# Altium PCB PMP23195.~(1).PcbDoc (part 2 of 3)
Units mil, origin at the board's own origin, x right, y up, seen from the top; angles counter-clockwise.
Board outline 3600 x 3000 mil, 4 copper layers (Top Layer, Signal Layer 1, Signal Layer 2, Bottom Layer), stack 39.6 mil thick; 143 components, 62 nets, 279 pads, 97 vias.
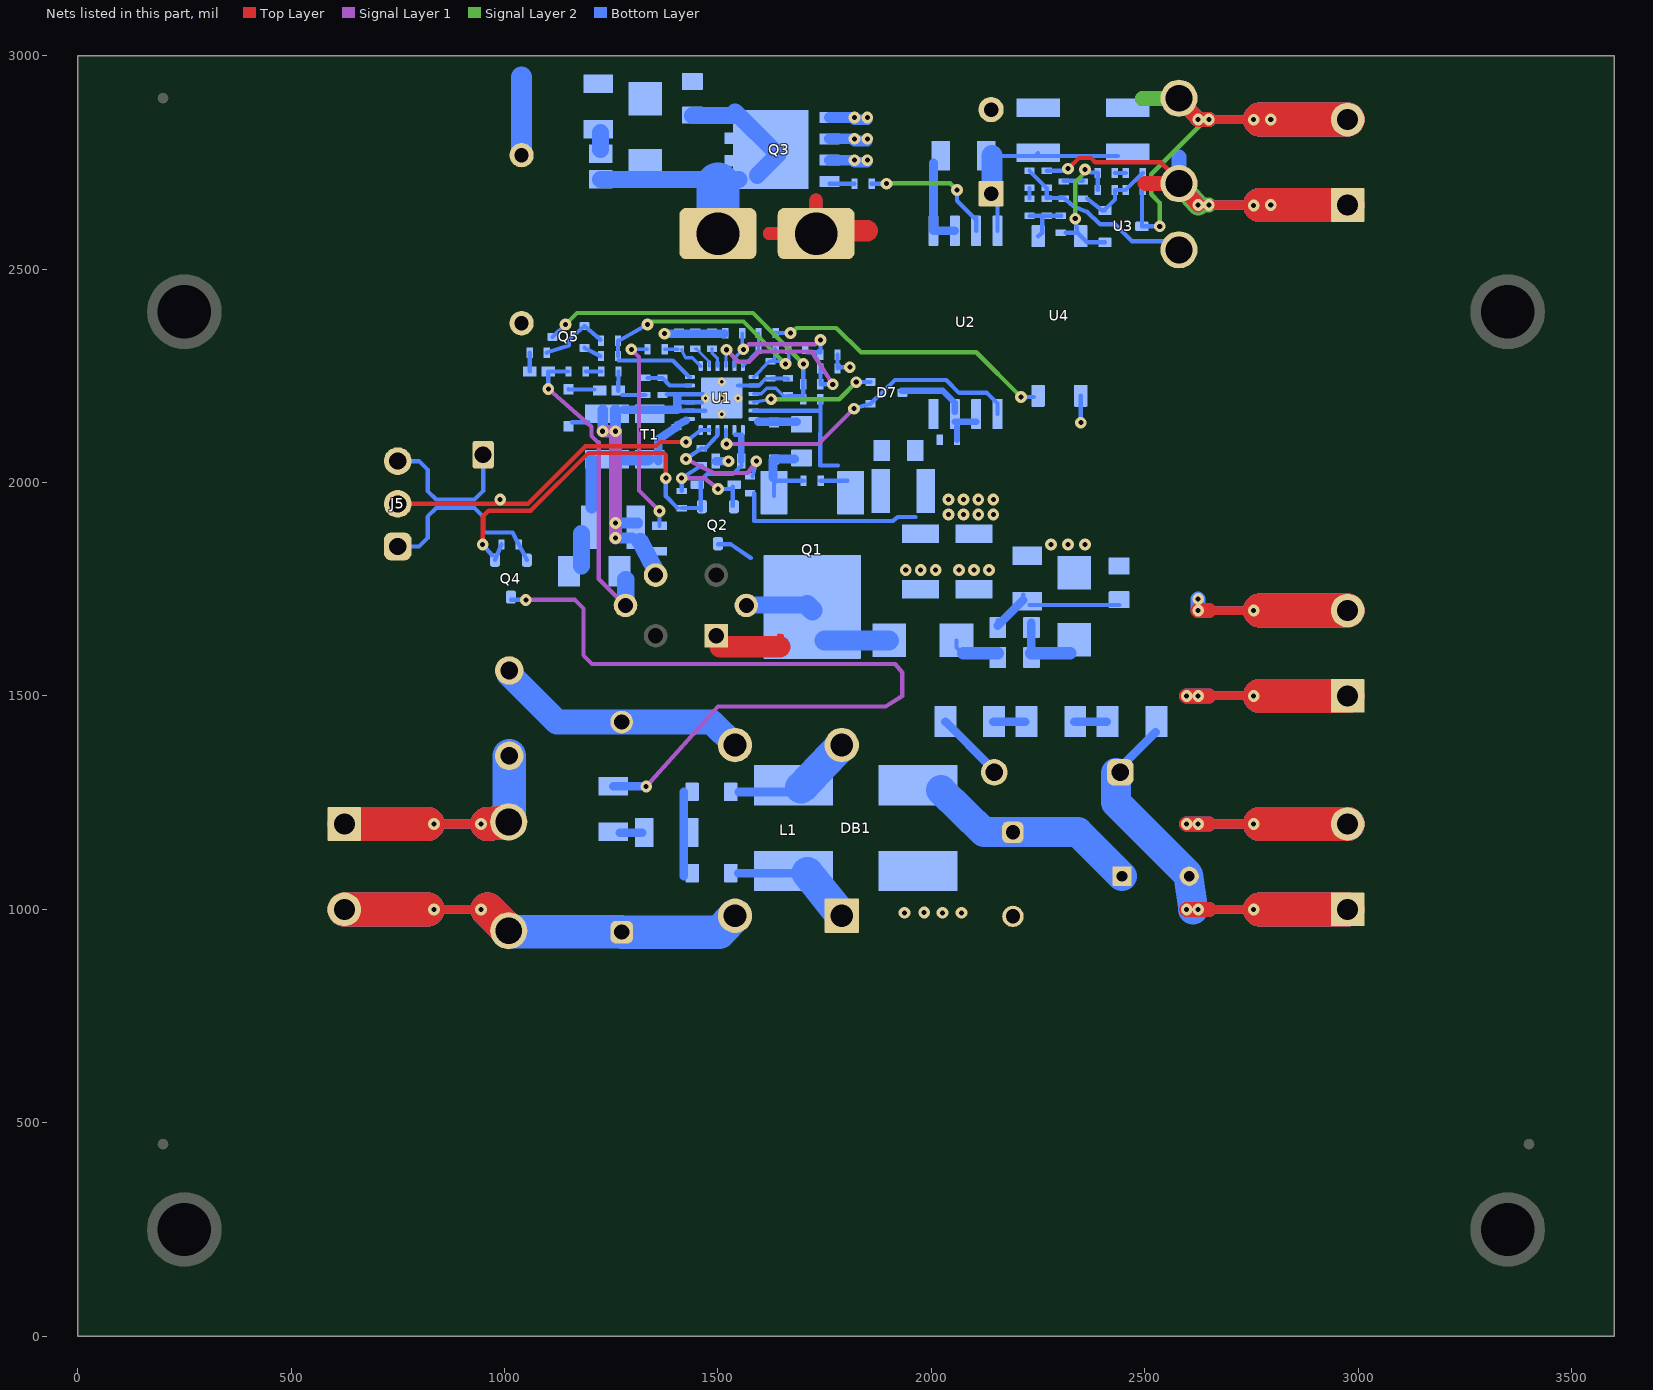
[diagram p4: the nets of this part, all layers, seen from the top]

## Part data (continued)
D8: library part CMP-0077082-2, "Diode, Standard Recovery Rectifier, 1000 V, 1 A, AEC-Q101, SMA", Manufacturer="ON Semiconductor", Value1=1A, Value2=1.1V
D9: library part CMP-0084982-1, "Diode, TVS, Uni, 150 V, 243 Vc, 400 W, 1.6 A, SMA", Manufacturer=Littelfuse, Value1=243V
D10: library part CMP-0084980-1, "Diode, TVS, Uni, 120 V, 193 Vc, 400 W, 2.1 A, SMA", Manufacturer=Littelfuse, Value1=193V
D11: library part CMP-0076957-3, "Diode, Switching, 75 V, 0.3 A, SOD-523", Manufacturer="Micro Commercial Components", Value1=0.3A, Value2=1.25V
D12: library part CMP-0085774-1, "Diode, Zener, 27 V, 300 mW, AEC-Q101, SOD-323", Manufacturer="ON Semiconductor", Power_W=300mW, Value1=0.3W
D13: library part CMP-0005889-5, "Diode, Zener, 39 V, 350 mW, AEC-Q101, SOD-523", Manufacturer="Diodes Inc.", Power_W=350mW, Value1=0.35W
DB1: "Diode, P-N-Bridge, 600 V, 4 A, Z4-D", Manufacturer="Comchip Technology", Supplier Part Number 1=641-1502-1-ND, Value1=4A, Value2=0.95V
F1: library part CMP-0003561-2, "Fuse, 3.15 A, 250VAC/VDC, TH", Irating_A=3.15A, Manufacturer=Littelfuse, Supplier Part Number 1=F5504CT-ND
FID1 FID2 FID3 FID4 FID5 FID6: library part CMP-0077181-1, "Fiducial mark.  There is nothing to buy or mount.", Manufacturer=N/A
H1 H2 H3 H4: library part CMP-0003617-1, "Machine Screw, Round, #4-40 x 1/4, Nylon, Philips panhead", Manufacturer="B&F Fastener Supply", Supplier Part Number 1=H542-ND
H5 H6 H7 H8: library part CMP-0003610-1, "Standoff, Hex, 0.5\"L #4-40 Nylon", Manufacturer=Keystone, Supplier Part Number 1=36-1902C-ND
J1 J2 J3 J4: library part CMP-0074910-1, "Terminal Block, 5.08 mm, 2x1, Brass, TH", Color=Blue, Current_A=15A, Manufacturer="On-Shore Technology", Supplier Part Number 1=ED1609-ND, Voltage_V=300V
J5: library part CMP-0075407-2, "Header, 100mil, 3x1, Gold, TH", Color=Black, Current_A=6.3A, Manufacturer=Samtec, Supplier Part Number 1=SAM1029-03-ND, Voltage_V=550V
L1: library part CMP-0092946-1, "Common Mode Choke, 2.3mH 35%, 0.6x0.38x0.75 IN", Manufacturer=Renco, Operating Temperature Range=to, Test Frequency=10kHz, Tolerance_%=35%
L2: library part CMP-0087546-1, "WE-FI Leaded Toroidal Line Choke", Manufacturer=Wurth
LBL1: library part CMP-0003625-1, "Thermal Transfer Printable Labels, 0.650\" W x 0.200\" H - 10,000 per roll", Manufacturer=Brady, Supplier Part Number 1=97C5133
Logo1 Logo7 Logo8 Logo10 Logo12 Logo13: library part CMP-0074835-1, "IEC 61010-1 High Voltage Warning"
Logo2 Logo9 Logo11 Logo14: library part CMP-0074837-1, "IEC 61010-1 Hot Surface Warning"
Logo3 Logo15: library part CMP-0074838-1, "Texas Instrument Corporate Signature", PartNumber="Texas Instruments"
Logo4: library part CMP-0074847-1, "FCC_disclaimer"
Logo5: library part CMP-0074769-1
Logo6: library part CMP-0074844-1
Logo16 Logo17: library part CMP-0074836-1, "IEC 61010-1 Caution Warning"
Q1: library part CMP-0083711-2, "MOSFET, N-CH, 800 V, 8 A, DPAK", Alternate Manufacturer=None, Manufacturer="Infineon Technologies", Supplier Part Number 1=IPD80R600P7ATMA1CT-ND, Value1="? ohm", Value2="20 nC"
Q2: library part CMP-0081263-2, "MOSFET, N-CH, Depletion Mode, 800 V, SOT-23", Alternate Manufacturer=None, Manufacturer=IXYS, Supplier Part Number 1=CLA4160-1-ND, Value1="? ohm", Value2="? nC"
Q3: library part CMP-0001046-2, "MOSFET, N-CH, 150 V, 87 A, PG-TDSON-8", Alternate Manufacturer=None, Manufacturer="Infineon Technologies", Supplier Part Number 1=BSC093N15NS5ATMA1CT-ND, Value2="33 nC"
Q4: library part CMP-0067574-2, "MOSFET, N-CH, Depletion Mode, 100 V, 0.17 A, AEC-Q101, SOT-23", Alternate Manufacturer=None, Manufacturer="Infineon Technologies", Supplier Part Number 1=BSS126H6327XTSA2CT-ND, Value1="? ohm", Value2="1.4 nC"
Q5: library part CMP-0077878-2, "Transistor, PNP, 40 V, 0.2 A, AEC-Q101, SOT-323", Manufacturer="Diodes Inc.", Value1="0.2 A", Value2=300.0
R1: library part CMP-0026333-2, "RES, 3.32 k, 1%, 0.063 W, AEC-Q200 Grade 0, 0402", Manufacturer=Vishay-Dale, Power_W=63mW, Supplier Part Number 1=541-3.32KLCT-ND, TempCo="100 ppm/C", Tolerance_%=1%, Value2=0.063W, Value_Code=3k32, ValueDisplayed=3.32k
R2: library part CMP-0020554-3, "RES, 470 k, 5%, 0.125 W, AEC-Q200 Grade 0, 0805", Manufacturer=Vishay-Dale, Power_W=125mW, Supplier Part Number 1=541-470KACT-ND, TempCo="200 ppm/C", Tolerance_%=5%, Value2=0.125W, Value_Code=470k
R3 R4: library part CMP-0018589-3, "RES, 13 k, 5%, 0.25 W, AEC-Q200 Grade 0, 1206", Manufacturer=Vishay-Dale, Power_W=250mW, Supplier Part Number 1=541-13KECT-ND, TempCo="200 ppm/C", Tolerance_%=5%, Value2=0.25W, Value_Code=13k0, ValueDisplayed=13k
R5 R7: library part CMP-0020464-3, "RES, 15, 5%, 0.125 W, AEC-Q200 Grade 0, 0805", Manufacturer=Vishay-Dale, Power_W=125mW, Supplier Part Number 1=541-15ACT-ND, TempCo="200 ppm/C", Tolerance_%=5%, Value2=0.125W, Value_Code=15R0, ValueDisplayed=15
R6 R10 R24: library part CMP-0026859-2, "RES, 1.0 M, 5%, 0.063 W, AEC-Q200 Grade 0, 0402", Manufacturer=Vishay-Dale, Power_W=63mW, Supplier Part Number 1=541-1.0MJCT-ND, TempCo="200 ppm/C", Tolerance_%=5%, Value2=0.063W, Value_Code=1M00, ValueDisplayed=1.0M
R8: library part CMP-0026038-3, "RES, 169 k, 1%, 0.063 W, AEC-Q200 Grade 0, 0402", Manufacturer=Vishay-Dale, Power_W=63mW, Supplier Part Number 1=541-169KLCT-ND, TempCo="100 ppm/C", Tolerance_%=1%, Value2=0.063W, Value_Code=169k
R9: library part CMP-0026609-3, "RES, 93.1 k, 1%, 0.063 W, AEC-Q200 Grade 0, 0402", Manufacturer=Vishay-Dale, Power_W=63mW, Supplier Part Number 1=541-93.1KLCT-ND, TempCo="100 ppm/C", Tolerance_%=1%, Value2=0.063W, Value_Code=93k1, ValueDisplayed=93.1k
R11: library part CMP-0026827-3, "RES, 10, 5%, 0.063 W, AEC-Q200 Grade 0, 0402", Manufacturer=Vishay-Dale, Power_W=63mW, Supplier Part Number 1=541-10JCT-ND, TempCo="200 ppm/C", Tolerance_%=5%, Value2=0.063W, Value_Code=10R0, ValueDisplayed=10
R12: library part CMP-0018578-3, "RES, 10, 5%, 0.25 W, AEC-Q200 Grade 0, 1206", Manufacturer=Vishay-Dale, Power_W=250mW, Supplier Part Number 1=541-10ECT-ND, TempCo="200 ppm/C", Tolerance_%=5%, Value2=0.25W, Value_Code=10R0, ValueDisplayed=10
R13: library part CMP-0026327-2, "RES, 39.2 k, 1%, 0.063 W, AEC-Q200 Grade 0, 0402", Manufacturer=Vishay-Dale, Power_W=63mW, Supplier Part Number 1=541-39.2KLCT-ND, TempCo="100 ppm/C", Tolerance_%=1%, Value2=0.063W, Value_Code=39k2, ValueDisplayed=39.2k
R14: library part CMP-0026063-3, "RES, 191 k, 1%, 0.063 W, AEC-Q200 Grade 0, 0402", Manufacturer=Vishay-Dale, Power_W=63mW, Supplier Part Number 1=541-191KLCT-ND, TempCo="100 ppm/C", Tolerance_%=1%, Value2=0.063W, Value_Code=191k
R15: library part CMP-0020445-3, "RES, 100, 5%, 0.125 W, AEC-Q200 Grade 0, 0805", Manufacturer=Vishay-Dale, Power_W=125mW, Supplier Part Number 1=541-100ACT-ND, TempCo="200 ppm/C", Tolerance_%=5%, Value2=0.125W, Value_Code=100R, ValueDisplayed=100
R16 R29 R41: library part CMP-0025958-3, "RES, 10.0 k, 1%, 0.063 W, AEC-Q200 Grade 0, 0402", Manufacturer=Vishay-Dale, Power_W=63mW, Supplier Part Number 1=541-10.0KLCT-ND, TempCo="100 ppm/C", Tolerance_%=1%, Value2=0.063W, Value_Code=10k0, ValueDisplayed=10.0k
R17: library part CMP-0081856-1, "RES, 0, 0%, 0.2 W, AEC-Q200 Grade 0, 0402", Manufacturer=Vishay-Dale, Power_W=200mW, Supplier Part Number 1=541-0.0YBTR-ND, Tolerance_%=0%, Value2=0.2W, Value_Code=0
R18 R27: library part CMP-0026436-2, "RES, 511, 1%, 0.063 W, AEC-Q200 Grade 0, 0402", Manufacturer=Vishay-Dale, Power_W=63mW, Supplier Part Number 1=541-511LCT-ND, TempCo="100 ppm/C", Tolerance_%=1%, Value2=0.063W, Value_Code=511R, ValueDisplayed=511
R19: library part CMP-0026366-2, "RES, 402, 1%, 0.063 W, AEC-Q200 Grade 0, 0402", Manufacturer=Vishay-Dale, Power_W=63mW, Supplier Part Number 1=541-402LCT-ND, TempCo="100 ppm/C", Tolerance_%=1%, Value2=0.063W, Value_Code=402R, ValueDisplayed=402
R20: library part CMP-0026028-3, "RES, 15.4 k, 1%, 0.063 W, AEC-Q200 Grade 0, 0402", Manufacturer=Vishay-Dale, Power_W=63mW, Supplier Part Number 1=541-15.4KLCT-ND, TempCo="100 ppm/C", Tolerance_%=1%, Value2=0.063W, Value_Code=15k4, ValueDisplayed=15.4k
R21: library part CMP-0015175-2, "RES, 0.22, 1%, 0.5 W, 1210", Manufacturer=Rohm, Power_W=500mW, Supplier Part Number 1=RHM.22SCT-ND, TempCo="200 ppm/C", Tolerance_%=1%, Value2=0.5W, Value_Code=R220, ValueDisplayed=0.22
R22: library part CMP-0027004-2, "RES, 0, 5%, 0.063 W, 0402", Manufacturer="Yageo America", Power_W=63mW, Supplier Part Number 1=311-0.0JRCT-ND, TempCo="200 ppm/C", Tolerance_%=5%, Value2=0.063W, Value_Code=0000, ValueDisplayed=0
R23: library part CMP-0026518-2, "RES, 6.98 k, 1%, 0.063 W, AEC-Q200 Grade 0, 0402", Manufacturer=Vishay-Dale, Power_W=63mW, Supplier Part Number 1=541-6.98KLCT-ND, TempCo="100 ppm/C", Tolerance_%=1%, Value2=0.063W, Value_Code=6k98, ValueDisplayed=6.98k
R25: library part CMP-0026669-1, "RES, 150 k, 1%, 0.1 W, AEC-Q200 Grade 0, 0402", Manufacturer=Panasonic, Power_W=100mW, Supplier Part Number 1=P150KLCT-ND, TempCo="100 ppm/C", Tolerance_%=1%, Value2=0.1W, Value_Code=150k
R26: library part CMP-0026027-3, "RES, 15.0 k, 1%, 0.063 W, AEC-Q200 Grade 0, 0402", Manufacturer=Vishay-Dale, Power_W=63mW, Supplier Part Number 1=541-15.0KLCT-ND, TempCo="100 ppm/C", Tolerance_%=1%, Value2=0.063W, Value_Code=15k0, ValueDisplayed=15.0k
R28: library part CMP-0021844-3, "RES, 0.68, 1%, 0.125 W, AEC-Q200 Grade 0, 0805", Manufacturer=Panasonic, Power_W=125mW, Supplier Part Number 1=P.68DCT-ND, TempCo="250 ppm/C", Tolerance_%=1%, Value2=0.125W, Value_Code=R680, ValueDisplayed=0.68
R30: library part CMP-0026162-2, "RES, 20.0 k, 1%, 0.063 W, AEC-Q200 Grade 0, 0402", Manufacturer=Vishay-Dale, Power_W=63mW, Supplier Part Number 1=541-20.0KLCT-ND, TempCo="100 ppm/C", Tolerance_%=1%, Value2=0.063W, Value_Code=20k0, ValueDisplayed=20.0k
R31: library part CMP-0078244-2, "RES, 30.0 k, 1%, 0.063 W, AEC-Q200 Grade 0, 0402", Manufacturer=Vishay-Dale, Power_W=63mW, Supplier Part Number 1=541-30.0KLCT-ND, TempCo="100 ppm/C", Tolerance_%=1%, Value2=0.063W, Value_Code=30k0, ValueDisplayed=30.0k
R32: library part CMP-0026467-2, "RES, 5.62 k, 1%, 0.063 W, AEC-Q200 Grade 0, 0402", Manufacturer=Vishay-Dale, Power_W=63mW, Supplier Part Number 1=541-5.62KLCT-ND, TempCo="100 ppm/C", Tolerance_%=1%, Value2=0.063W, Value_Code=5k62, ValueDisplayed=5.62k
R33 R34 R35: library part CMP-0018628-3, "RES, 220 k, 5%, 0.25 W, AEC-Q200 Grade 0, 1206", Manufacturer=Vishay-Dale, Power_W=250mW, Supplier Part Number 1=541-220KECT-ND, TempCo="200 ppm/C", Tolerance_%=5%, Value2=0.25W, Value_Code=220k
R36: library part CMP-0025953-3, "RES, 102, 1%, 0.063 W, AEC-Q200 Grade 0, 0402", Manufacturer=Vishay-Dale, Power_W=63mW, Supplier Part Number 1=541-102LCT-ND, TempCo="100 ppm/C", Tolerance_%=1%, Value2=0.063W, Value_Code=102R, ValueDisplayed=102
R37 R38: library part CMP-0026229-2, "RES, 2.10 k, 1%, 0.063 W, AEC-Q200 Grade 0, 0402", Manufacturer=Vishay-Dale, Power_W=63mW, Supplier Part Number 1=541-2.10KLCT-ND, TempCo="100 ppm/C", Tolerance_%=1%, Value2=0.063W, Value_Code=2k10, ValueDisplayed=2.10k
R39: library part CMP-0026213-2, "RES, 27.4 k, 1%, 0.063 W, AEC-Q200 Grade 0, 0402", Manufacturer=Vishay-Dale, Power_W=63mW, Supplier Part Number 1=541-27.4KLCT-ND, TempCo="100 ppm/C", Tolerance_%=1%, Value2=0.063W, Value_Code=27k4, ValueDisplayed=27.4k
R40: library part CMP-0026071-3, "RES, 1.00 k, 1%, 0.063 W, AEC-Q200 Grade 0, 0402", Manufacturer=Vishay-Dale, Power_W=63mW, Supplier Part Number 1=541-1.00KLCT-ND, TempCo="100 ppm/C", Tolerance_%=1%, Value2=0.063W, Value_Code=1k00, ValueDisplayed=1.00k
RT1: library part CMP-0002523-3, "Thermistor NTC, 47k ohm, 5%, 0603", Manufacturer=MuRata, Power_W=100mW, Supplier Part Number 1=490-2428-1-ND, Tolerance_%=5%
SH-J1: library part CMP-0077139-2, "Shunt, 100mil, Tin plated, Black", Color=Black, Current_A=4.3A, Manufacturer=Samtec, Supplier Part Number 1=SAM8972-ND
T1: library part CMP-0094252-2, "Transformer FLYBACK for UCC28781EVM-053", Manufacturer=Renco, Operating Temperature Range=to, Voltage_Isolation_Vrms=3kV
TP1 TP3: library part CMP-0055148-1, "Test Point, Multipurpose, Black, TH", Color=Black, Manufacturer=Keystone, PartNumber=5011, Supplier Part Number 1=36-5011-ND
TP2 TP4 TP5: library part CMP-0055149-1, "Test Point, Multipurpose, White, TH", Color=White, Manufacturer=Keystone, PartNumber=5012, Supplier Part Number 1=36-5012-ND
U1: library part CMP-0094229-1, "Zero-Voltage-Switching Flyback Controller with Dedicated Synchronous Rectifier Gate-Drive", Manufacturer="Texas Instruments", Max Supply Voltage=34V, Min Supply Voltage=14V, Nominal Supply Current=235-3000uA, Operating Temperature Range="-40°C to +125°C", Switching Frequency=1.5kHz
U2: library part CMP-0860377-2, "4-A/6-A, Single-Channel Reinforced Isolation Gate Driver with High Noise Immunity, DWV0008A (SOIC-8)", Alternate Manufacturer="Texas Instruments"
U3: library part CMP-0066199-1, "2.5V Low Iq Adjustable Precision Shunt Regulator, DBZ0003A (SOT-23-3)", Alternate Manufacturer="Texas Instruments"
U4: library part CMP-0087394-2, "Optoisolator Transistor Output 5000Vrms 1 Channel 6-SO", Manufacturer=Toshiba
ZZ1: library part CMP-0077236-1
ZZ2: library part CMP-0077237-1
ZZ3: library part CMP-0077238-1
ZZ4: library part CMP-0003615-1, "This Assembly Note will show in the PcbDoc and associated outputs"

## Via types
v1: diameter 27.56, hole 11.81, Top Layer to Bottom Layer, tented top, 38 vias
v2: diameter 27.56, hole 11.81, Top Layer to Bottom Layer, tented both sides, 34 vias
v3: diameter 27.56, hole 11.81, Top Layer to Bottom Layer, 20 vias
v4: diameter 19.68, hole 7.87, Top Layer to Bottom Layer, 5 vias

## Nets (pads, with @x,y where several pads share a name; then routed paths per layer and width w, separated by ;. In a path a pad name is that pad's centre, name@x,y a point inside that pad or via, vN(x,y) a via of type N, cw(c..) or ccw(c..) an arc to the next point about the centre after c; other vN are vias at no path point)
BUR: C13.1 R13.1 R14.2 U1.5 | length 341.5
  Signal Layer 1 w9.84: v2@1556.4,2311.9 v2(1559.42,2311.9) v2@1562.38,2314.85
  Signal Layer 1 w10: v2(1559.42,2311.9) 1572.52,2324 1728,2324 v2(1740,2334)
  Bottom Layer w7.87: U1.5@1538.49,2272.53 1538.49,2290.97 v2(1559.42,2311.9) 1557.1,2314.23 C13.1@1557.14,2349.3
  Bottom Layer w10: R14.2@1710,2305 1740,2305 v2(1740,2334)
CS: C21.1 Q5.3 R6.2 R19.1 U1.9 | length 865.4
  Signal Layer 2 w10: v2(1143,2370) 1170,2397 1582,2397 v2(1700,2278)
  Bottom Layer w8: U1.9@1583.77,2207.57 1601,2207.57 1614.11,2220.69 1635.37,2220.69 1654.29,2201.77 C21.1@1664.11,2201.77
  Bottom Layer w10: Q5.3@1112.61,2341 v2(1143,2370) ; C21.1@1664,2202 1700,2202 R6.2@1700,2230 v2(1700,2278)
FB: C14.2 R30.1 U1.6 | length 92.7
  Bottom Layer w7.87: U1.6@1558.18,2272.53 1594.9,2309.25 1594.9,2312.88 R30.1@1595,2350
FLT: C19.2 R1.2 U1.1 | length 98.2
  Bottom Layer w7.87: C19.2@1401.98,2311.9 1402.3,2311.58 C19.2@1404.27,2311.58 ; 1423.95,2291.9 1440.38,2291.9 U1.1@1459.75,2272.53
  Bottom Layer w8: R1.2@1375,2312 C19.2@1405.98,2312 ; C19.2@1415,2310.91 1423.95,2291.9
GND_P: C4.1 C5.1 C10.2 C11.2 C12.2 C13.2 C17.2 C18.1 C19.1 C20.2 C21.2 C22.1 C23.2 C24.1 D12.1 J3.2 J5.3 R8.1 R9.1 R13.2 R17.1 R21.1 R23.1 R28.2 RT1.2 T1.7 T1.8 U1.8 U1.20 U1.21 U1.22 U1.25 U2.4 U4.4 | length 3639.5
  Top Layer w20: v3@2630,1700 2770,1700
  Top Layer w35: v3@2625,1699.77 2650,1699.77
  Top Layer w80: 2770,1700 J3.2@2975,1700
  Signal Layer 1 w20: v3@2630,1700 2770,1700
  Signal Layer 1 w30: v1(1230,2120) v1(1260,2120) v1(1260,1870)
  Signal Layer 1 w80: 2770,1700 J3.2@2975,1700
  Signal Layer 2 w20: v3@2630,1700 2770,1700
  Signal Layer 2 w80: 2770,1700 J3.2@2975,1700
  Bottom Layer w7.87: C12.2@1612.58,2243.67 C12.2@1624.99,2243.67
  Bottom Layer w8: 1596.16,2227.25 C12.2@1612.58,2243.67
  Bottom Layer w8.66: U1.21@1434.16,2187.49 U1.21@1434.16,2187.88
  Bottom Layer w10: J5.3@750,2050 800,2050 820,2030.1 820,1980 840,1960 930,1960 950,1980 T1.8@950,2065 ; D12.1@1158,2141 C18.1@1196.18,2141 ; R23.1@1380,2207 U1.25@1465,2207 ; 1405,2188 U1.25@1462.6,2188 ; C17.2@1413.2,2168.2 U1.25@1470,2168.2 ; C13.2@1516.51,2348.67 C13.2@1517.14,2349.3 ; U1.25@1547.35,2227.25 1596.16,2227.25 ; C24.1@1585,1975 1585,1910 1910,1910 1921,1919 1963,1919 ; C12.2@1624.99,2243.67 1662.21,2243.67 C21.2@1664.11,2241.77 ; R17.1@1780,2267 R13.2@1780,2299 ; R17.1@1780,2270 v2(1809,2270) ; v1(2350,2140) U4.4@2350,2202.99
  Bottom Layer w20: C18.1@1280,2170 1405,2170 1405,2201.74 ; v2(1375,2348.67) C13.2@1516.51,2348.67 ; C23.2@1495,2050 v2(1525,2050) ; v3@2630,1700 2770,1700
  Bottom Layer w25: v1(1230,2120) C18.1@1230,2170 ; v1(1260,1870) C22.1@1300,1870 ; v1(1260,1905) C22.1@1312.35,1905 ; v1(1260,2120) C18.1@1260,2170
  Bottom Layer w35: v3(2625,1727) 2625,1699.77 2650,1699.77
  Bottom Layer w40: C22.1@1318,1862 T1.7@1359,1783.75
  Bottom Layer w80: 2770,1700 J3.2@2975,1700
  other v1: 2040,1925 2075,1925 2110,1925 2145,1925 2040,1960 2075,1960 2110,1960 2145,1960
  other v3: 2625,1700 2755,1700
  other v4: 1508.96,2159.54 1470.78,2197.72 1508.96,2197.72 1547.15,2197.72 1508.96,2235.91
GND_P0: C1.2 C2.2 DB1.4 J2.2 R35.1 | length 1645.6
  Top Layer w20: v1@2630,1200 2770,1200
  Top Layer w35: v1(2598,1200) 2650,1200
  Top Layer w80: 2770,1200 J2.2@2975,1200
  Signal Layer 1 w20: v1@2630,1200 2770,1200
  Signal Layer 1 w80: 2770,1200 J2.2@2975,1200
  Signal Layer 2 w20: v1@2630,1200 2770,1200
  Signal Layer 2 w80: 2770,1200 J2.2@2975,1200
  Bottom Layer w10: C2.2@2137.66,1321.77 C2.2@2137.66,1335.25
  Bottom Layer w20: R35.1@2032.91,1440 C2.2@2137.66,1335.25 ; v1@2630,1200 2770,1200
  Bottom Layer w35: v1(2598,1200) 2650,1199.77
  Bottom Layer w80: 2770,1200 J2.2@2975,1200
  other v1: 1936.75,992.02 2026.32,992.02 2070.71,992.02 1983.18,992.75 2625,1200
  other v3: 2755,1200
GND_S: C7.2 C8.2 C9.2 C16.2 C20.1 C26.2 D10.2 J4.2 Q3.1 Q3.2 Q3.3 R12.1 R31.2 TP3.1 U2.5 U2.6 U3.3 | length 2959
  Top Layer w20: v3(2650,2850) 2770,2850
  Top Layer w35: TP3.1@2580,2900 v3(2625,2850) v3(2650,2850)
  Top Layer w80: 2770,2850 v3(2795,2850) J4.2@2975,2850
  Signal Layer 1 w20: v3(2650,2850) 2770,2850
  Signal Layer 1 w35: TP3.1@2580,2900 v3(2625,2850) v3(2650,2850)
  Signal Layer 1 w80: 2770,2850 v3(2795,2850) J4.2@2975,2850
  Signal Layer 2 w10: v2(2535,2600) 2535,2655 2515,2675 2515,2722 v3@2641.5,2848.5
  Signal Layer 2 w20: v3(2650,2850) 2770,2850
  Signal Layer 2 w35: 2495,2900 TP3.1@2580,2900 v3(2625,2850) v3(2650,2850)
  Signal Layer 2 w80: 2770,2850 v3(2795,2850) J4.2@2975,2850
  Bottom Layer w10: R31.2@2495,2685 2493.31,2683.31 U3.3@2493.31,2600 v2(2535,2600)
  Bottom Layer w20: C8.2@2005,2748.43 U2.5@2005,2589.57 U2.6@2055,2589.57 ; v3(2650,2850) 2770,2850
  Bottom Layer w25: Q3.3@1761.22,2755 v1(1820,2755) ; Q3.2@1761.22,2805 v1(1820,2805) ; Q3.1@1761.22,2855 v1(1820,2855) ; v1@1820,2750 v1@1850,2750 ; v1@1820,2800 v1@1850,2800 ; v1@1820,2850 v1@1850,2850 ; v3(2625,2850) v3(2650,2850)
  Bottom Layer w35: 2495,2900 TP3.1@2580,2900 v3(2625,2850) v3(2650,2850)
  Bottom Layer w50: C20.1@1040,2766.85 1040,2950
  Bottom Layer w80: 2770,2850 v3(2795,2850) J4.2@2975,2850
  other v1: 1850,2755 1850,2805 1850,2855
  other v3: 2755,2849.81
IPC: R6.1 R17.2 U1.4 | length 418
  Signal Layer 1 w10: v2(1519.8,2310.91) 1548,2283 1572.52,2283 1597.27,2307 1719,2307 v2(1769,2230)
  Bottom Layer w7.87: U1.4@1518.81,2272.53 1518.81,2309.92 v2(1519.8,2310.91)
  Bottom Layer w10: R6.1@1740,2230 v2@1775,2230 ; R6.1@1740,2235 R17.2@1740,2267
NetC1_1: C1.1 DB1.1 L2.1 | length 507
  Bottom Layer w70: DB1.1@2022.69,1279.42 2122.91,1180.99 2190.68,1180.99 2343.24,1180.99 L2.1@2446.59,1077.65
NetC3_1: C3.1 J1.2 L1.2 TP2.1 | length 2169.5
  Top Layer w20: 820,1000 960,1000
  Top Layer w80: J1.2@625,1000 820,1000 ; 960,1000 TP2.1@1010,950
  Signal Layer 1 w20: 820,1000 960,1000
  Signal Layer 1 w80: J1.2@625,1000 820,1000 ; 960,1000 TP2.1@1010,950
  Signal Layer 2 w20: 820,1000 960,1000
  Signal Layer 2 w80: J1.2@625,1000 820,1000 ; 960,1000 TP2.1@1010,950
  Bottom Layer w10: TP2.1@1007.28,947.72 TP2.1@1013.52,947.72
  Bottom Layer w20: 820,1000 960,1000
  Bottom Layer w78.74: TP2.1@1013.52,947.72 1273.59,947.72 C3.1@1274.58,946.74 1500,946.74 ; 1502.5,946.74 L1.2@1540,985
  Bottom Layer w80: J1.2@625,1000 820,1000 ; 960,1000 TP2.1@1010,950
  other v3: 835,1000 945,1000
NetC3_2: C3.2 F1.1 L1.3 | length 606
  Bottom Layer w59.06: F1.1@1011.02,1559.54 1011.02,1550.91 1123.06,1438.87 C3.2@1274.58,1438.87 1485,1438.87 L1.3@1540,1385
NetC6_2: C6.2 R2.1 R5.2 | length 302.6
  Bottom Layer w10: R5.2@2155.63,1675 R5.2@2155.63,1677.48 ; C6.2@2215,1730.72 C6.2@2215,1736.85 ; C6.2@2230,1712.75 R2.1@2440,1712.75
  Bottom Layer w20: R5.2@2155.63,1665 C6.2@2215,1724.37
NetC11_1: C11.1 D7.3 U2.2 U2.3 | length 238.6
  Bottom Layer w15: D7.3@1930,2215 1960,2215 2027,2215 2055,2186.94 U2.3@2055,2165 ; U2.3@2055,2142 U2.2@2105,2142 ; C11.1@2060,2100 U2.3@2060,2130
NetC15_1: C15.1 R12.2 | length 40
  Bottom Layer w39.37: C15.1@1225,2780 R12.2@1225,2820
NetC15_2: C15.2 C16.1 D10.1 Q3.5 Q3.6 Q3.7 Q3.8 Q3.9 T1.B | length 762.8
  Bottom Layer w39.37: C15.2@1225,2710 Q3.9@1550,2710 ; C16.1@1440,2860 Q3.9@1550,2860 ; Q3.9@1539.77,2868.47 1640.44,2767.8 Q3.9@1592.02,2719.38
  Bottom Layer w100: T1.B@1500,2583 1500,2700
NetC25_1: C25.1 R27.2 | length 25
  Bottom Layer w10: R27.2@2230,2665 C25.1@2230,2690
NetC27_1: C27.1 R29.1 | length 25
  Bottom Layer w10: C27.1@2430,2725 R29.1@2455,2725
NetC27_2: C27.2 C28.1 R32.1 U3.1 U4.3 | length 331
  Signal Layer 2 w10: v2(2337,2618) 2337.09,2703 2360,2725.91 v2(2360,2733)
  Bottom Layer w10: R32.1@2315,2585 U4.3@2342.01,2585 ; v2(2337,2618) U4.3@2342.01,2585 ; v2(2360,2733) 2373.02,2725.91 2389.09,2725.91 C27.2@2390,2725 C28.1@2390,2685 ; U3.1@2406.69,2562.6 2364.41,2562.6 U4.3@2350,2577.01 U4.3@2342.01,2585
NetC28_2: C28.2 R25.1 R29.2 R31.1 U3.2 | length 190.1
  Bottom Layer w10: R25.1@2365,2665 2399.71,2637.4 U3.2@2406.69,2637.4 2406.69,2639.82 2430,2663.13 C28.2@2430,2685 R31.1@2455,2685 R29.2@2495,2725
NetD1_1: D1.1 D2.1 R3.1 | length 197.4
  Bottom Layer w20: 1420,1077.65 1420.34,1275
NetD1_2: D1.2 DB1.3 L1.1 | length 250.6
  Bottom Layer w20: 1547.35,1085 DB1.3@1669.85,1085
  Bottom Layer w75: DB1.3@1710,1085 L1.1@1790,985
NetD2_2: D2.2 DB1.2 L1.4 | length 258.9
  Bottom Layer w20: 1549.28,1275 DB1.2@1670.28,1275
  Bottom Layer w75: DB1.2@1695,1285 L1.4@1790,1385
NetD5_2: D5.2 Q1.1 R15.2 R16.2 | length 194.2
  Bottom Layer w10: Q1.1@1631.43,1968.39 1631.43,1998.29 1636.97,2003.83 R16.2@1700.72,2003.83
  Bottom Layer w20: Q1.1@1629,2011 D5.2@1629,2053.69 ; D5.2@1630,2055 R15.2@1680,2055
NetD6_1: D6.1 Q2.2 R18.2 R24.1 | length 259.4
  Signal Layer 1 w10: v2(1415,2010) 1468.25,2010 v2(1500,1985)
  Bottom Layer w10: R24.1@1415,1980 v2(1415,2010) R18.2@1462,2040 ; v2(1500,1985) 1535,1985 ; Q2.2@1535,1945 D6.1@1535,1990
NetD8_1: D8.1 R7.1 | length 102.1
  Bottom Layer w10: D8.1@2058.74,1630 2058.74,1613.64 D8.1@2062.38,1610
  Bottom Layer w30: D8.1@2075,1600 R7.1@2155.63,1600
NetD9_1: D9.1 R5.1 R7.2 | length 161.5
  Bottom Layer w20: R7.2@2234.37,1600 R5.1@2234.37,1670.83
  Bottom Layer w30: R7.2@2234.37,1600 D9.1@2325,1600
NetD11_1: D11.1 R20.1 R38.2 | length 99
  Bottom Layer w10: D11.1@1266.65,2215 R38.2@1267,2260 ; D11.1@1276,2205 R20.1@1330,2205
NetD11_2: D11.2 D12.2 | length 60
  Bottom Layer w10: D12.2@1150,2218.31 D11.2@1210,2218
NetD13_1: D13.1 R41.2 | length 44
  Bottom Layer w10: R41.2@1059,2304 D13.1@1059.35,2260
NetF1_2: F1.2 J1.1 TP1.1 | length 1696.5
  Top Layer w20: 820,1200 960,1200
  Top Layer w80: J1.1@625,1200 820,1200 ; 960,1200 TP1.1@1010,1205
  Signal Layer 1 w20: 820,1200 960,1200
  Signal Layer 1 w80: J1.1@625,1200 820,1200 ; 960,1200 TP1.1@1010,1205
  Signal Layer 2 w20: 820,1200 960,1200
  Signal Layer 2 w80: J1.1@625,1200 820,1200 ; 960,1200 TP1.1@1010,1205
  Bottom Layer w20: 820,1200 960,1200
  Bottom Layer w78.74: TP1.1@1009.58,1204.61 1011.02,1206.05 F1.2@1011.02,1359.54
  Bottom Layer w80: J1.1@625,1200 820,1200 ; 960,1200 TP1.1@1010,1205
  other v3: 835,1200 945,1200
NetJ5_1: J5.1 Q4.2 R10.1 | length 453.7
  Bottom Layer w10: J5.1@750,1850 800,1850 820,1870 820,1920 840,1940 930,1940 950,1920 950,1883 1019,1883 Q4.2@1052.4,1818.31
NetQ3_4: Q3.4 R11.2 | length 58.8
  Bottom Layer w10: Q3.4@1761.22,2700 R11.2@1820,2700
NetQ4_3: Q4.3 R4.2 | length 1875.3
  Signal Layer 1 w10: v2(1050,1725) 1165,1725 1185,1705 1185,1595 1205,1575 1915,1575 1931.97,1555 1931.97,1500 1892.39,1475 1500,1475 v2(1332,1288.15)
  Bottom Layer w10: Q4.3@1015,1725 v2(1050,1725)
  Bottom Layer w20: R4.2@1255,1288.15 v2(1332,1288.15)
NetQ5_1: Q5.1 R40.2 R41.1 | length 166.2
  Bottom Layer w10: R41.1@1099,2304 1150.94,2321 1150.94,2335 Q5.1@1187.42,2366.59 R40.2@1224.37,2334
NetQ5_2: Q5.2 R39.2 | length 41.7
  Bottom Layer w10: Q5.2@1187.42,2315.41 R39.2@1224.37,2296
NetR3_2: R3.2 R4.1 | length 53.2
  Bottom Layer w20: R4.1@1269.67,1180 R3.2@1322.91,1180
NetR25_2: R25.2 R36.2 | length 45.1
  Bottom Layer w10: R36.2@2309.88,2706.59 R25.2@2355,2706.59
NetR26_1: R26.1 R27.1 R32.2 U4.1 | length 127.8
  Bottom Layer w10: R27.1@2230,2625 R26.1@2270,2625 R32.2@2305,2625 ; U4.1@2250,2577.01 2260,2585 R26.1@2260,2625
NetR33_1: R33.1 R34.2 | length 75.6
  Bottom Layer w20: R34.2@2335,1440 R33.1@2410.55,1440
NetR34_1: R34.1 R35.2 | length 75
  Bottom Layer w20: R35.2@2145,1440 R34.1@2220,1440
NetR37_2: R37.2 R38.1 | length 37
  Bottom Layer w10: R37.2@1190,2260 R38.1@1227,2260
OPTO_C: R30.2 U4.6 | length 676
  Signal Layer 2 w10: v2(1670,2350) 1685,2362 1777,2362 1835,2305 2105,2305 v1(2210,2200)
  Bottom Layer w10: R30.2@1635,2350 v2(1670,2350) ; v1(2210,2200) U4.6@2240,2200
P13: C23.1 D6.2 Q2.1 Q4.1 R10.2 R24.2 U1.13 U1.14 | length 1064.7
  Top Layer w10: v2@949.01,1850 949,1920 963,1934 1061.63,1934 1196.63,2069 1373.5,2069 1378,2064.5 v2(1378,2010)
  Bottom Layer w10: v2(949,1855) Q4.1@971.51,1829 ; Q4.1@977.6,1818.31 R10.2@993,1855 ; v2(1378,2010) 1378,1968 R24.2@1405,1940 ; R24.2@1415,1940 Q2.1@1452.77,1940 ; Q2.1@1460,1935 1460,2005 1475,2020 1535,2020 C23.1@1555,2040 ; U1.14@1540,2112 U1.13@1556.22,2111.97
  Bottom Layer w15: C23.1@1555,2050 1555,2109
PWML: D5.1 R15.1 U1.12 | length 90
  Bottom Layer w20: 1595,2142 R15.1@1685,2142
QLSRC: Q1.3 R16.1 R19.2 R21.2 R28.1 U1.11 | length 414.8
  Bottom Layer w10: U1.11@1585,2168 1740,2168 ; R16.1@1739.97,2003.83 Q1.3@1803.72,2003.83 ; R19.2@1740,2195 1739.97,2040 1781,2040
RDM: R9.2 U1.3 | length 45.8
  Bottom Layer w7.87: R9.2@1485.96,2312.88 1485.96,2303.52 1499.12,2290.36 U1.3@1499.12,2272.53
REF: C12.1 C14.1 R14.1 R39.1 R40.1 U1.7 U1.24 | length 839.7
  Signal Layer 2 w9.84: 1560,2377 v2(1658,2278) ; v2@1659.44,2269.49 v2@1664.53,2274.58
  Signal Layer 2 w10: v2@1340,2377 1560,2377
  Bottom Layer w8: U1.7@1583.77,2246.94 1620.5,2283.67 C12.1@1624.99,2283.67 ; C14.1@1634.9,2312.88 1632.61,2312.88 1632.61,2291.29 C12.1@1624.99,2283.67 ; R14.1@1665.76,2314.85 1665.76,2275.81 1664.53,2274.58 1655.44,2283.67 C12.1@1624.99,2283.67
  Bottom Layer w9.84: U1.24@1432.72,2246.94 U1.24@1434.16,2246.94
  Bottom Layer w10: R39.1@1266,2296 R40.1@1266,2332 ; R40.1@1266,2331 v2(1335,2370) ; R39.1@1267.65,2286 1394,2286 U1.24@1432.72,2246.94
RT1_1: R1.1 RT1.1 | length 487.6
  Signal Layer 1 w9.84: v2(1297,2312) 1315,2294 ; v2@1297.34,2310.91 v2@1306.49,2310.91
  Signal Layer 1 w10: 1315,2294 1315,1981 v2(1363,1933)
  Bottom Layer w8: v2(1297,2312) R1.1@1335,2312
  Bottom Layer w10: RT1.1@1362.93,1898.9 v2(1363,1933)
RTZ: R8.2 U1.2 | length 56
  Bottom Layer w6: R8.2@1446.59,2312.88 1450.15,2312.88 1479.44,2283.59 U1.2@1479.44,2272.53
RUN: D7.2 U1.10 | length 301.1
  Signal Layer 2 w9.84: v2(1624.74,2195.03) 1784,2195
  Signal Layer 2 w10: 1784,2195.03 v2(1824,2235)
  Bottom Layer w7.87: U1.10@1583.77,2187.88 v2(1624.74,2195.03) v2@1617.59,2187.88
  Bottom Layer w10: v2(1824,2235) D7.2@1857.6,2235.59
SR_DRV: R11.1 U2.7 | length 325.9
  Signal Layer 2 w10: v2(1895,2700) 1895.7,2700.7 2044.3,2700.7 v2(2060,2685)
  Bottom Layer w10: R11.1@1860,2700 v2(1895,2700) ; v2(2060,2685) 2060,2660 U2.7@2105,2615 ; U2.7@2105,2589.57 U2.7@2105,2620
SRDRV: D7.1 U1.15 U2.1 | length 773.7
  Signal Layer 1 w10: v2(1520,2090) 1735.67,2090 v2(1818.64,2172.96)
  Bottom Layer w10: v2@1519,2090 U1.15@1519,2123 ; v2(1818.64,2172.96) D7.1@1857.6,2184.41 1915,2240 2035,2240 2065,2210 2130,2210 U2.1@2155,2185 ; U2.1@2155,2160.43 U2.1@2155,2184.84
SWS: C24.2 R18.1 U1.16 | length 324.3
  Signal Layer 1 w10: v2(1425,2055) 1490,2022 1570,2022 v2(1590,2050)
  Bottom Layer w10: v2(1425,2055) R18.1@1462,2080 ; R18.1@1470,2079.04 1499.2,2110 U1.16@1499.12,2122.92 ; C24.2@1580.79,2014.3 v2(1590,2050)
Vaux: D3.2 D13.2 R37.1 T1.6 | length 745.1
  Signal Layer 1 w10: v2(1102.65,2219) 1204,2130.77 1204,2109.23 1219.23,2094 1221,2094 1221,1774 T1.6@1290,1705
  Bottom Layer w10: v2(1102.65,2219) D13.2@1102.65,2260 R37.1@1150,2260
  Bottom Layer w40: T1.6@1284,1713 D3.2@1284,1773
Vbulk: C4.2 C5.2 C6.1 D9.2 J3.1 R2.2 T1.1 | length 1735.3
  Top Layer w10: 1643.41,1641.75 1645.16,1640 1650,1640
  Top Layer w20: v3@2630,1500 2770,1500
  Top Layer w35: v3(2598,1500) 2650,1500
  Top Layer w50: T1.1@1505,1615 1645,1615
  Top Layer w80: 2770,1500 J3.1@2975,1500
  Signal Layer 1 w20: v3@2630,1500 2770,1500
  Signal Layer 1 w25: v3(2598,1500) 2650,1500
  Signal Layer 1 w80: 2770,1500 J3.1@2975,1500
  Signal Layer 2 w20: v3@2630,1500 2770,1500
  Signal Layer 2 w25: v3(2598,1500) 2650,1500
  Signal Layer 2 w80: 2770,1500 J3.1@2975,1500
  Bottom Layer w20: v3@2630,1500 2770,1500
  Bottom Layer w35: v3(2598,1500) 2650,1500
  Bottom Layer w80: 2770,1500 J3.1@2975,1500
  other v1: 1940,1795 1975,1795 2010,1795 2065,1795 2100,1795 2135,1795 2280,1855 2320,1855 2360,1855
  other v3: 2625,1500 2755,1500
Vbulk0: C2.1 J2.1 L2.2 R33.2 | length 2112.7
  Top Layer w20: v1@2630,1000 v3(2755,1000) 2770,1000
  Top Layer w35: v1(2598,1000) 2650,1000
  Top Layer w80: 2770,1000 J2.1@2975,1000
  Signal Layer 1 w20: v1@2630,1000 v3(2755,1000) 2770,1000
  Signal Layer 1 w35: v1@2598,999.77 2650,999.77
  Signal Layer 1 w80: 2770,1000 J2.1@2975,1000
  Signal Layer 2 w20: v1@2630,1000 v3(2755,1000) 2770,1000
  Signal Layer 2 w35: v1(2598,1000) 2650,1000
  Signal Layer 2 w80: 2770,1000 J2.1@2975,1000
  Bottom Layer w20: C2.1@2430,1320 R33.2@2525,1415 ; v1@2630,1000 v3(2755,1000) 2770,1000
  Bottom Layer w35: v1@2598,999.77 2650,999.77
  Bottom Layer w70: C2.1@2432.81,1319.77 2432.91,1250 2601.59,1080.99 v1@2613,1000
  Bottom Layer w80: 2770,1000 J2.1@2975,1000
  other v1: 2625,1000
VDD: C10.1 C17.1 C18.2 C22.2 D3.1 U1.19 | length 363
  Bottom Layer w18: C17.1@1405,2135 U1.19@1425,2145
  Bottom Layer w20: C10.1@1360,2050 1360,2100 C17.1@1403,2130
  Bottom Layer w30: C22.2@1204.46,1941.82 C18.2@1205,2050 ; C18.2@1281.04,2054.85 C10.1@1336.04,2054.85
  Bottom Layer w40: 1180,1805 C22.2@1180,1880
VOUT: C7.1 C8.1 C9.1 C26.1 J4.1 R22.1 T1.A TP4.1 U2.8 | length 3122
  Top Layer w10: v2(2320,2735) 2346,2760 2374,2760 2384,2750.05 2537.36,2750 2580,2706.97 TP4.1@2580,2700
  Top Layer w20: v3(2625,2650) v3(2650,2650) 2770,2650
  Top Layer w30: 1621.13,2583 T1.A@1651.13,2583 ; T1.A@1730,2632 1730,2662
  Top Layer w35: 2500,2700 TP4.1@2580,2700 v3(2625,2650)
  Top Layer w50: T1.A@1700,2590 1850,2590
  Top Layer w80: 2770,2650 v3(2795,2650) J4.1@2975,2650
  Signal Layer 1 w20: v3(2625,2650) v3(2650,2650) 2770,2650
  Signal Layer 1 w30: 1621.13,2583 T1.A@1651.13,2583 ; T1.A@1730,2632 1730,2662 ; T1.A@1809,2583 1839,2583
  Signal Layer 1 w35: 2505,2700 TP4.1@2580,2700 v3(2625,2650)
  Signal Layer 1 w39.37: T1.A@1676.91,2582.25 1686.43,2582.25 T1.A@1676.91,2591.78
  Signal Layer 1 w40: T1.A@1700,2590 T1.A@1775,2590
  Signal Layer 1 w80: 2770,2650 v3(2795,2650) J4.1@2975,2650
  Signal Layer 2 w20: v3(2650,2650) 2770,2650
  Signal Layer 2 w35: v3(2625,2650) v3(2650,2650)
  Signal Layer 2 w50: TP4.1@2580,2700 v3(2625,2650)
  Signal Layer 2 w80: 2770,2650 v3(2795,2650) J4.1@2975,2650
  Bottom Layer w10: C7.1@2141.93,2678.5 C7.1@2140,2676.57 2155,2661.57 U2.8@2155,2589.57 ; C8.1@2141.93,2765 C9.1@2243.15,2765 ; C9.1@2250,2771.85 C9.1@2243.15,2765 ; R22.1@2270,2730 2310,2730 v2(2320,2735) ; C26.1@2436.8,2765 C9.1@2243.15,2765
  Bottom Layer w20: v3(2650,2650) 2770,2650
  Bottom Layer w25: v3@2625.32,2650 v3(2650,2650)
  Bottom Layer w35: 2580,2762.93 TP4.1@2580,2700 v3(2625,2650)
  Bottom Layer w50: C7.1@2141.93,2678.5 C8.1@2141.93,2765
  Bottom Layer w80: 2770,2650 v3(2795,2650) J4.1@2975,2650
  other v3: 2755,2648.84
VOUT_A: C25.2 R22.2 R26.2 R36.1 TP5.1 | length 432.9
  Bottom Layer w10: C25.2@2230,2730 R22.2@2270,2690 R26.2@2270,2665 ; R26.2@2274.88,2666.59 2309.88,2666.59 2331.74,2648 2365,2634 2395.28,2605 2430,2605 2470,2565 2560,2565 TP5.1@2580,2545
VS: R20.2 R23.2 U1.23 | length 106.7
  Bottom Layer w10: R20.2@1335,2245 R23.2@1370,2245 1387,2227.25 U1.23@1434.16,2227.25
Vswn: D8.2 Q1.2 Q2.3 T1.2 | length 399.4
  Bottom Layer w7.87: Q1.2@1721.2,1700.68 Q1.2@1721.2,1708.55
  Bottom Layer w10: Q2.3@1500,1855 1530,1855 1577,1823
  Bottom Layer w40: T1.2@1571.5,1712.75 Q1.2@1709.12,1712.75
  Bottom Layer w47.24: Q1.2@1709.12,1712.75 Q1.2@1721.2,1700.68 ; Q1.2@1750,1630 D8.2@1900,1630
XCD: J5.2 U1.17 U1.18 | length 809.3
  Top Layer w10: J5.2@740,1950 1055,1950 1190,2085 1355,2085 1365,2095 v2(1425,2095)
  Bottom Layer w10: v2(1425,2095) U1.18@1459.75,2122.92 U1.17@1479.44,2122.92
  other v1: 990,1960
pads on no net: FID1.1 FID2.1 FID3.1 FID4.1 FID5.1 FID6.1 H1.1 H2.1 H3.1 H4.1 H5.0 H6.0 H7.0 H8.0 LBL1.0 SH-J1.0 T1.3 T1.5
copper on no net: | length 1.2
  Bottom Layer w12: 1344.22,1642.61 1345.08,1641.75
